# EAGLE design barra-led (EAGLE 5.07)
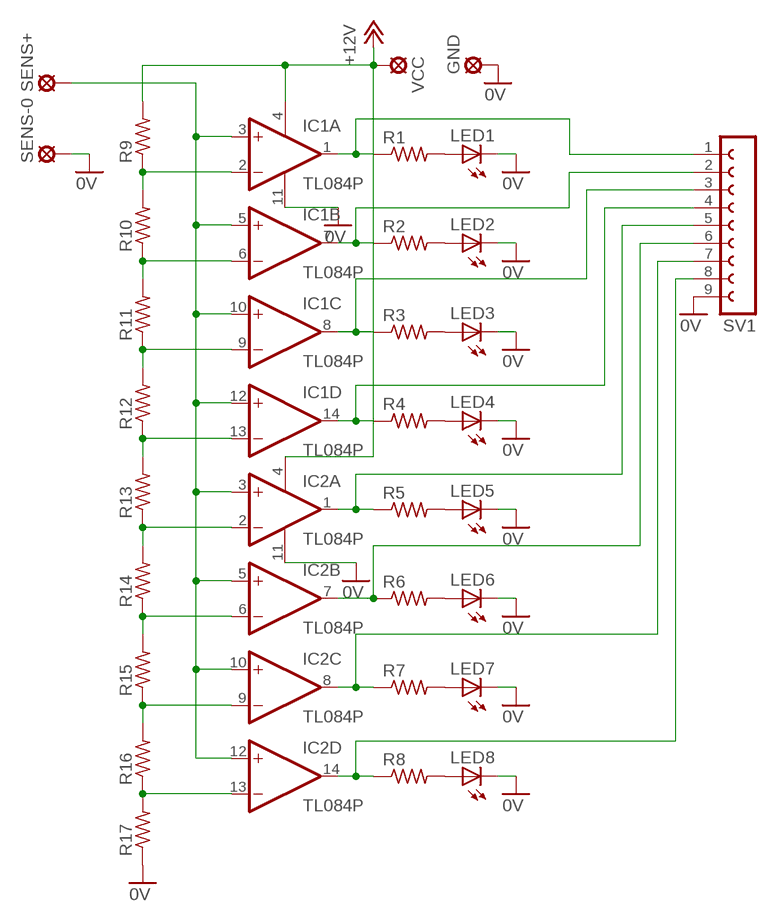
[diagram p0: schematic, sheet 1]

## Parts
GND  SE14  [SE14]
IC1  TL084P  [DIL14]
IC2  TL084P  [DIL14]
LED1  LED3MM  [LED3MM]
LED2  LED3MM  [LED3MM]
LED3  LED3MM  [LED3MM]
LED4  LED3MM  [LED3MM]
LED5  LED3MM  [LED3MM]
LED6  LED3MM  [LED3MM]
LED7  LED3MM  [LED3MM]
LED8  LED3MM  [LED3MM]
R1  R-US_0207/10  [0207/10]
R2  R-US_0207/10  [0207/10]
R3  R-US_0207/10  [0207/10]
R4  R-US_0207/10  [0207/10]
R5  R-US_0207/10  [0207/10]
R6  R-US_0207/10  [0207/10]
R7  R-US_0207/10  [0207/10]
R8  R-US_0207/10  [0207/10]
R9  R-US_0207/10  [0207/10]
R10  R-US_0207/10  [0207/10]
R11  R-US_0207/10  [0207/10]
R12  R-US_0207/10  [0207/10]
R13  R-US_0207/10  [0207/10]
R14  R-US_0207/10  [0207/10]
R15  R-US_0207/10  [0207/10]
R16  R-US_0207/10  [0207/10]
R17  R-US_0207/10  [0207/10]
SENS+  SE14  [SE14]
SENS-0  SE14  [SE14]
SV1  FE09-1  [FE09]
VCC  SE14  [SE14]

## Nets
0V: GND.MP IC1.11(P:V-) IC2.11(P:V-) LED1.K(C) LED2.K(C) LED3.K(C) LED4.K(C) LED5.K(C) LED6.K(C) LED7.K(C) LED8.K(C) R17.1 SENS-0.MP SV1.9
+12V: IC1.4(P:V+) IC2.4(P:V+) R9.2 VCC.MP
N$1: IC1.1(A:OUT) R1.1 SV1.1
N$2: IC1.7(B:OUT) R2.1 SV1.2
N$3: IC1.8(C:OUT) R3.1 SV1.3
N$4: IC1.14(D:OUT) R4.1 SV1.4
N$5: IC2.1(A:OUT) R5.1 SV1.5
N$6: IC2.7(B:OUT) R6.1 SV1.6
N$7: IC2.8(C:OUT) R7.1 SV1.7
N$8: IC2.14(D:OUT) R8.1 SV1.8
N$9: IC1.2(A:-IN) R9.1 R10.2
N$10: IC1.6(B:-IN) R10.1 R11.2
N$11: IC1.9(C:-IN) R11.1 R12.2
N$12: IC1.13(D:-IN) R12.1 R13.2
N$13: IC2.2(A:-IN) R13.1 R14.2
N$14: IC2.6(B:-IN) R14.1 R15.2
N$15: IC2.9(C:-IN) R15.1 R16.2
N$16: IC2.13(D:-IN) R16.1 R17.2
N$17: LED1.A R1.2
N$18: LED2.A R2.2
N$19: LED3.A R3.2
N$20: LED4.A R4.2
N$21: LED5.A R5.2
N$22: LED6.A R6.2
N$23: LED7.A R7.2
N$24: LED8.A R8.2
N$27: IC1.3(A:+IN) IC1.5(B:+IN) IC1.10(C:+IN) IC1.12(D:+IN) IC2.3(A:+IN) IC2.5(B:+IN) IC2.10(C:+IN) IC2.12(D:+IN) SENS+.MP

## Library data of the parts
GND SENS+ SENS-0 VCC = solpad:SE14: SOLDER PAD
IC1 IC2 = linear:TL084: OP AMP
LED1-LED8 = led:LED: LED
R1-R17 = resistor:R-US_: RESISTOR, American symbol
SV1 = con-lsta:FE09-1: FEMALE HEADER

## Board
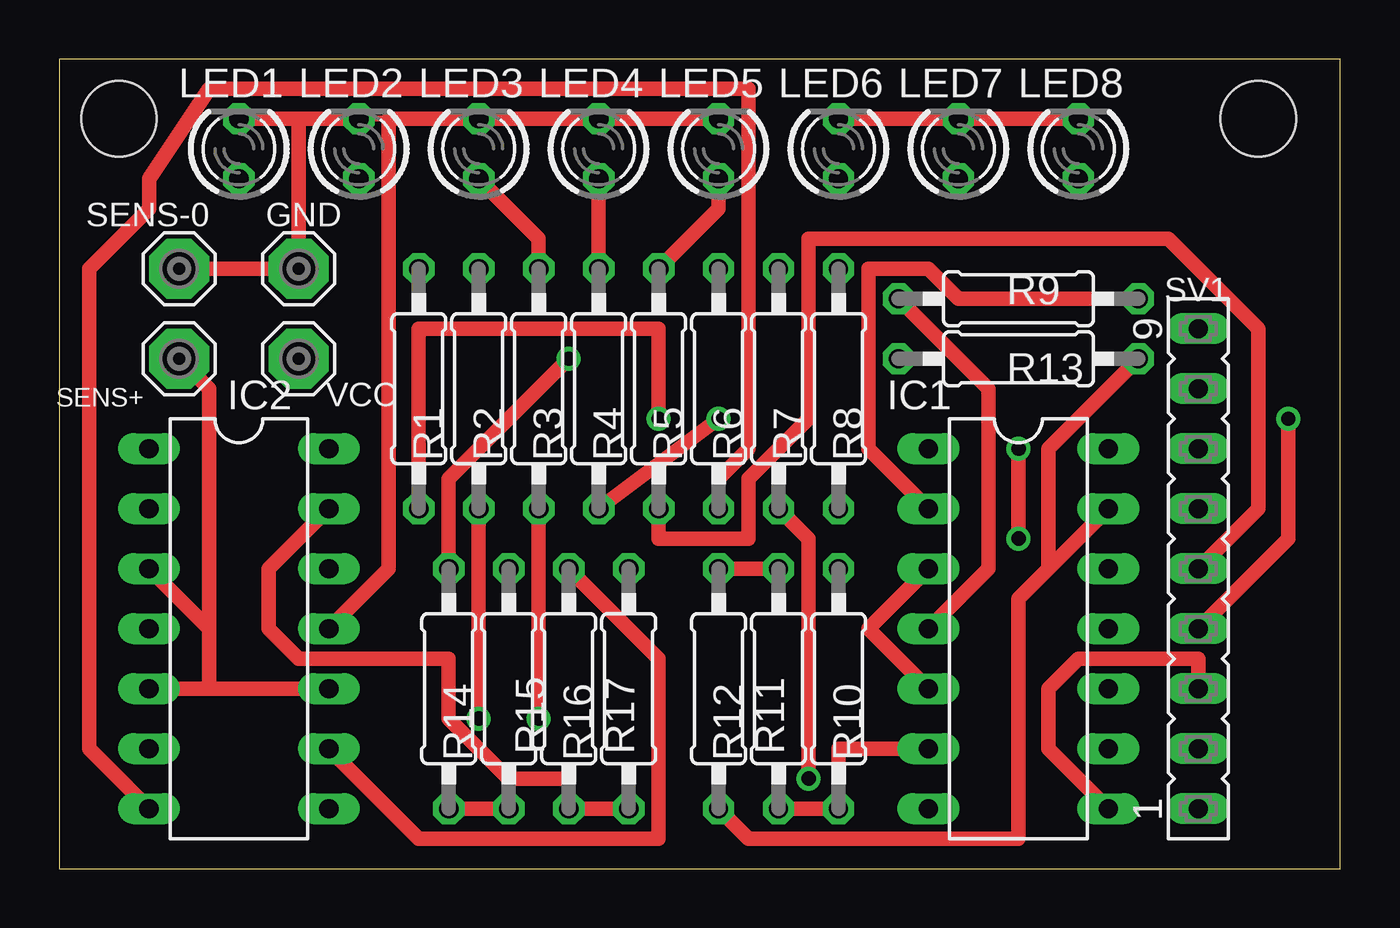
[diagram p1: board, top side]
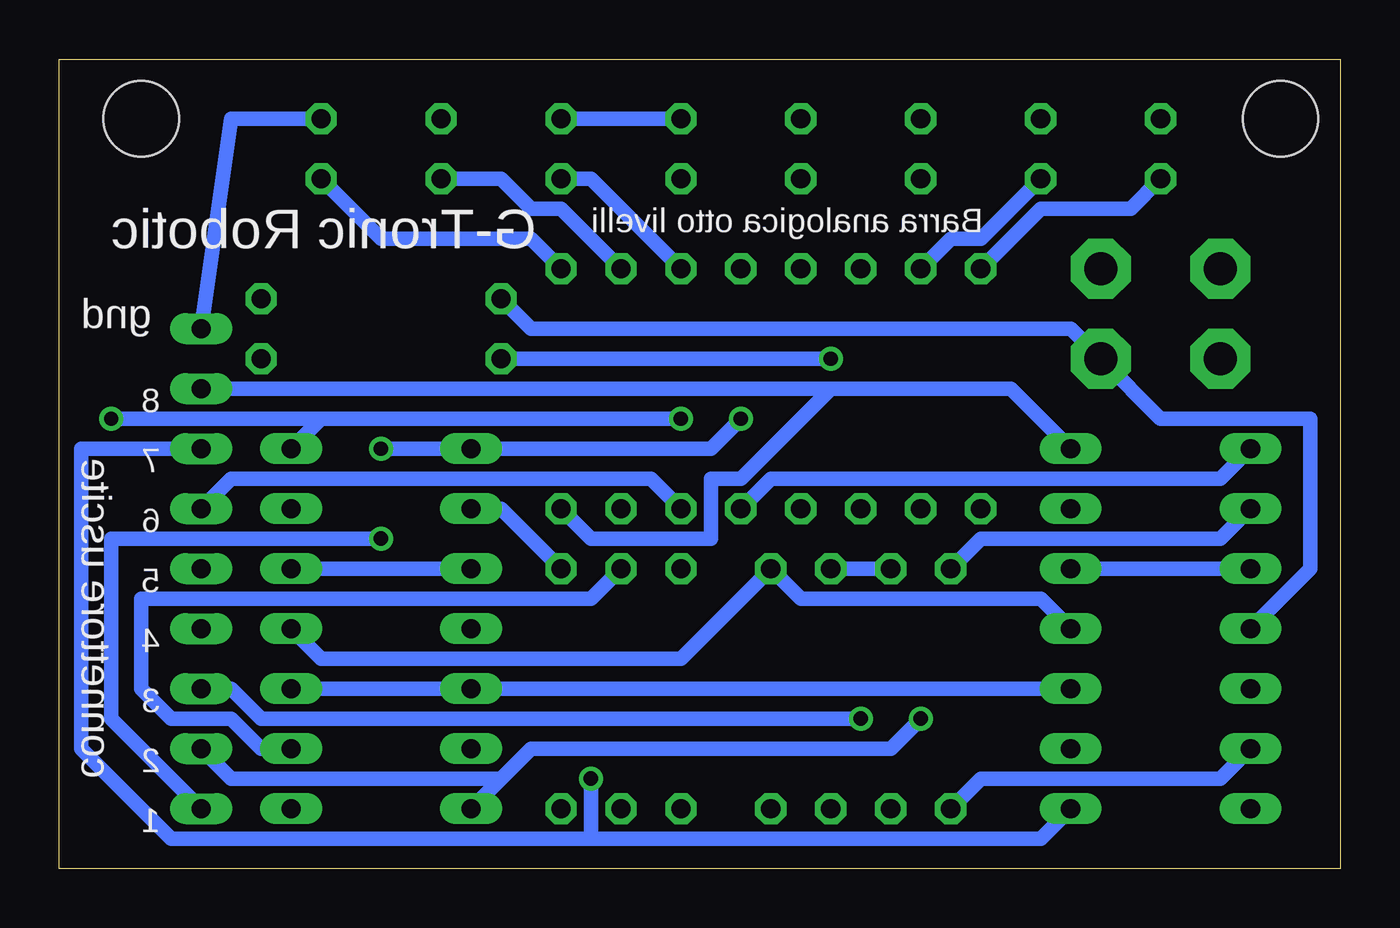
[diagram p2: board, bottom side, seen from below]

Size 54.28 x 34.28 mm. Coordinates in mm from the lower left corner, seen from the top.
Outline: 0,0 54.28,0 54.28,34.28 0,34.28 0,0
Copper layers (1*16): Top 0.035mm / dielectric 1.5mm / Bottom 0.035mm
Design rules "default": minimum track width 10mil, minimum drill 24mil, track to track 8mil, track to pad 8mil, pad to pad 8mil, via to via 8mil, smd to smd 8mil, copper to edge 40mil, drill to drill 8mil, minimum pad ring 10mil, minimum via ring 8mil, stop-mask expansion 4mil, vias tented up to drill 0mil, thermal gap 10mil
Holes 3.2 mm at 50.8,31.75 2.54,31.75

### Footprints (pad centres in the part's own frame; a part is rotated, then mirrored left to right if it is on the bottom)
SE14 = drill 1.397 pad 2.54 octagon: MP 0,0
DIL14 = drill 0.813 long: 1 -7.62,-3.81; 2 -5.08,-3.81; 3 -2.54,-3.81; 4 0,-3.81; 5 2.54,-3.81; 6 5.08,-3.81; 7 7.62,-3.81; 8 7.62,3.81; 9 5.08,3.81; 10 2.54,3.81; 11 0,3.81; 12 -2.54,3.81; 13 -5.08,3.81; 14 -7.62,3.81
LED3MM = drill 0.813 octagon: A -1.27,0; K 1.27,0
0207/10 = drill 0.813 octagon: 1 -5.08,0; 2 5.08,0
FE09 = drill 0.813 long: 1 -10.16,0; 2 -7.62,0; 3 -5.08,0; 4 -2.54,0; 5 0,0; 6 2.54,0; 7 5.08,0; 8 7.62,0; 9 10.16,0

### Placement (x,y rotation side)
GND  10.16,25.4 0 top
IC1  40.64,10.16 270 top
IC2  7.62,10.16 270 top
LED1  7.62,30.48 90 top
LED2  12.7,30.48 90 top
LED3  17.78,30.48 90 top
LED4  22.86,30.48 90 top
LED5  27.94,30.48 90 top
LED6  33.02,30.48 90 top
LED7  38.1,30.48 90 top
LED8  43.18,30.48 90 top
R1  15.24,20.32 90 top
R2  17.78,20.32 90 top
R3  20.32,20.32 90 top
R4  22.86,20.32 90 top
R5  25.4,20.32 90 top
R6  27.94,20.32 90 top
R7  30.48,20.32 90 top
R8  33.02,20.32 90 top
R9  40.64,24.13 180 top
R10  33.02,7.62 90 top
R11  30.48,7.62 270 top
R12  27.94,7.62 90 top
R13  40.64,21.59 0 top
R14  16.51,7.62 90 top
R15  19.05,7.62 270 top
R16  21.59,7.62 90 top
R17  24.13,7.62 270 top
SENS+  5.08,21.59 0 top
SENS-0  5.08,25.4 0 top
SV1  48.26,12.7 90 top
VCC  10.16,21.59 0 top

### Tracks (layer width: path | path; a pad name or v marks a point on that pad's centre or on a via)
0V
  Top 0.254: 13.97,31.75 LED2.K
  Top 0.61: LED6.K LED7.K LED8.K | SENS-0.MP GND.MP 10.16,31.75 | LED2.K 10.16,31.75 | 10.16,31.75 LED1.K | LED5.K LED4.K LED3.K 13.97,31.75 13.97,12.7 IC2.11
  Bottom 0.61: IC2.11 12.7,11.43 22.86,11.43 R17.1 27.94,8.89 43.18,8.89 IC1.11 | SV1.9 46.99,31.75 LED8.K | LED5.K LED6.K
+12V
  Top 0.61: IC1.4 39.37,12.7 39.37,20.32 R9.2
  Bottom 0.61: IC2.4 1.27,12.7 1.27,19.05 7.62,19.05 VCC.MP 11.43,22.86 34.29,22.86 R9.2
N$1  (via drill 0.61)
  Top 0.61: R1.1 15.24,22.86 25.4,22.86 v25.4,19.05 | v40.64,17.78 v40.64,13.97
  Bottom 0.61: v25.4,19.05 26.67,17.78 IC1.1 v40.64,17.78 | SV1.1 52.07,6.35 52.07,13.97 v40.64,13.97
N$2  (via drill 0.61)
  Top 0.61: v17.78,6.35 R2.1
  Bottom 0.61: v17.78,6.35 19.05,5.08 34.29,5.08 35.56,3.81 | 35.56,3.81 IC1.7 | SV1.2 46.99,3.81 35.56,3.81
N$3  (via drill 0.61)
  Top 0.61: v20.32,6.35 R3.1 | IC1.8 41.91,5.08 41.91,7.62 43.18,8.89 48.26,8.89 SV1.3
  Bottom 0.254: 46.99,7.62 SV1.3
  Bottom 0.61: v20.32,6.35 45.72,6.35 46.99,7.62
N$4  (via drill 0.61)
  Top 0.61: R4.1 v27.94,19.05 | SV1.4 52.07,13.97 v52.07,19.05
  Bottom 0.61: v27.94,19.05 43.18,19.05 | 43.18,19.05 IC1.14 | 43.18,19.05 v52.07,19.05
N$5
  Top 0.61: SV1.5 50.8,15.24 50.8,22.86 46.99,26.67 31.75,26.67 31.75,19.05 29.21,16.51 29.21,13.97 25.4,13.97 R5.1
  Bottom 0.61: IC2.1 5.08,16.51 24.13,16.51 R5.1
N$6
  Top 0.254: 27.94,16.51 R6.1
  Top 0.61: IC2.7 1.27,5.08 1.27,25.4 3.81,27.94 3.81,29.21 6.35,33.02 29.21,33.02 29.21,17.78 27.94,16.51
  Bottom 0.61: SV1.6 46.99,16.51 29.21,16.51 R6.1
N$7  (via drill 0.61)
  Top 0.61: R7.1 31.75,13.97 v31.75,3.81
  Bottom 0.61: IC2.8 12.7,1.27 31.75,1.27 | 31.75,1.27 49.53,1.27 53.34,5.08 53.34,17.78 SV1.7 | 31.75,1.27 v31.75,3.81
N$8
  Bottom 0.61: IC2.14 13.97,20.32 21.59,20.32 | 21.59,20.32 SV1.8 | R8.1 31.75,13.97 26.67,13.97 26.67,16.51 25.4,16.51 21.59,20.32
N$9
  Top 0.61: R9.1 38.1,24.13 36.83,25.4 34.29,25.4 34.29,17.78 IC1.2
  Bottom 0.254: 35.56,15.24 IC1.2
  Bottom 0.61: R10.2 35.56,15.24
N$10
  Top 0.61: R11.2 R10.1 33.02,5.08 IC1.6
N$11
  Top 0.61: R12.2 R11.1
  Bottom 0.254: 45.72,5.08 IC1.9
  Bottom 0.61: 45.72,5.08 46.99,6.35 49.53,6.35 50.8,7.62 50.8,11.43 31.75,11.43 R11.1
N$12
  Top 0.61: R12.1 29.21,1.27 40.64,1.27 40.64,11.43 41.91,12.7 | 41.91,12.7 IC1.13 | R13.2 41.91,17.78 41.91,12.7
N$13  (via drill 0.61)
  Top 0.61: v21.59,21.59 16.51,16.51 R14.2
  Bottom 0.61: IC2.2 5.08,13.97 15.24,13.97 R14.2 | v21.59,21.59 R13.1
N$14
  Top 0.61: R14.1 R15.2
  Bottom 0.61: IC2.6 5.08,3.81 15.24,3.81 R14.1
N$15
  Top 0.61: IC2.9 15.24,1.27 25.4,1.27 25.4,8.89 R16.2
  Bottom 0.61: R16.2 R15.1
N$16
  Top 0.254: 21.59,3.81 R16.1
  Top 0.61: R16.1 R17.2 | IC2.13 8.89,12.7 8.89,10.16 10.16,8.89 16.51,8.89 16.51,6.35 19.05,3.81 21.59,3.81
N$17
  Bottom 0.61: LED1.A 8.89,27.94 12.7,27.94 R1.2
N$18
  Bottom 0.61: LED2.A 15.24,26.67 16.51,26.67 R2.2
N$19
  Top 0.61: LED3.A 20.32,26.67 R3.2
N$20
  Top 0.61: R4.2 LED4.A
N$21
  Top 0.61: R5.2 27.94,27.94 LED5.A
N$22
  Bottom 0.61: R6.2 31.75,29.21 LED6.A
N$23
  Bottom 0.61: R7.2 33.02,27.94 34.29,27.94 35.56,29.21 LED7.A
N$24
  Bottom 0.61: R8.2 34.29,26.67 40.64,26.67 LED8.A
N$27
  Top 0.61: 6.35,7.62 IC2.10 | IC2.5 6.35,7.62 | 6.35,10.16 IC2.3 | 6.35,7.62 6.35,10.16 | SENS+.MP 6.35,20.32 6.35,10.16 | IC1.3 34.29,10.16 IC1.5
  Bottom 0.61: IC1.3 IC1.12 | IC1.10 IC1.5 IC2.10 | IC2.3 IC2.12

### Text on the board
bNames: Barra analogica otto livelli | G-Tronic Robotic | gnd | 8 | 7 | 6 | 5 | 4 | 3 | 2 | connettore uscite | 1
